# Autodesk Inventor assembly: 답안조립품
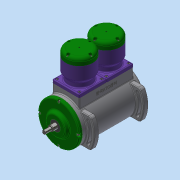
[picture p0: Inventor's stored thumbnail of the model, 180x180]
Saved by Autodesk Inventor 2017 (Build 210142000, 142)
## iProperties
Part Number: 답안조립품
Material: 일반
Document SubType Name: Assembly
Designer: Administrator
Mass: 7371.37 g
Surface Area: 5215.2 cm^2
Volume: 2062.19 cm^3
Density: 3.57453 g/cm^3
Author: Administrator
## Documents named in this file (16)
- C:\Users\Administrator\Desktop\620106V1009\답안조립품.iam
- C:\Users\Administrator\Desktop\620106V1009\본체.ipt
- C:\Users\Administrator\Desktop\620106V1009\실린더.ipt
- C:\Users\Administrator\Desktop\620106V1009\볼트 M4 x 12.ipt
- C:\Users\Administrator\Desktop\620106V1009\실린더헤드.ipt
- C:\Users\Administrator\Desktop\620106V1009\볼트 M5 x 20.ipt
- C:\Users\Administrator\Desktop\620106V1009\커넥팅로드 엔드.ipt
- C:\Users\Administrator\Desktop\620106V1009\커넥팅로드.ipt
- C:\Users\Administrator\Desktop\620106V1009\육각 머리 볼트 M4 x 16.ipt
- C:\Users\Administrator\Desktop\620106V1009\너트 M4.ipt
- C:\Users\Administrator\Desktop\620106V1009\피스톤.ipt
- C:\Users\Administrator\Desktop\620106V1009\피스톤핀.ipt
- C:\Users\Administrator\Desktop\620106V1009\베어링 6303.ipt
- C:\Users\Administrator\Desktop\620106V1009\크랭크축.ipt
- C:\Users\Administrator\Desktop\620106V1009\앞커버.ipt
- C:\Users\Administrator\Desktop\620106V1009\오일 실 17 x 32 x 8.ipt
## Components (4 placed, 2 different names)
1. 피스톤:1
2. 피스톤핀:1
3. 피스톤:2
4. 피스톤핀:2
## Named parameters: d38_d31 = 0, d39_d32 = 0, d40_d33 = 0, d41_d34 = 0, d42_d35 = 0, d43_d36 = 0, d44_d24 = 0, d45_d25 = 0, d46_d26 = 0, d47_d27 = 0, d48_d28 = 0, d49_d29 = 0, d50_d30 = 0
